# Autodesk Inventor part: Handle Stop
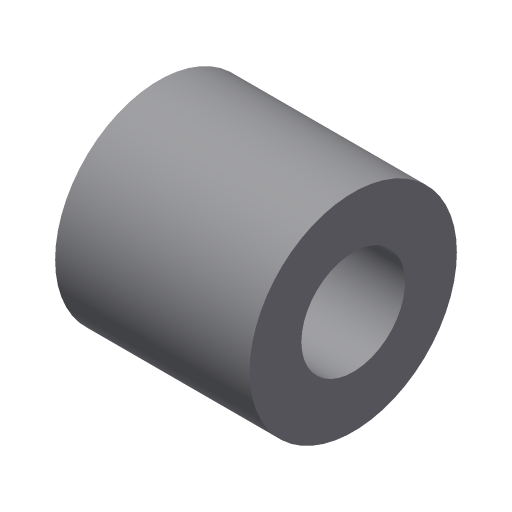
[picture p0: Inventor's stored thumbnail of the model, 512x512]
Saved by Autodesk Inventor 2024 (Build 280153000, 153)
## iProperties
Shininess: 77.0
Length Units: 11269
Angle Units: 11279
Time Units: 11290
Mass Units: 11283
Length Display Precision: 3
Angle Display Precision: 2
Compacted: True
Created: 2002-02
Part Number: Handle Stop
Document SubType Name: Modeling
Designer: ***
Density: 1 g/cm^3
Material: Generic
Mass: 2.36248 g
Surface Area: 14.8283 cm^2
Volume: 2.36248 cm^3
Appearance: Default
Density: 0.0
Volumn: 0.0
Area: 0.0
PropertySet Name: Model Information
Control State: 0
Master: False
Checked Out: False
Author: ***
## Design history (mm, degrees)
sketch "Sketch1"
  geometry: L1 (0, 0)-(0, -2); L2 (0, -2)-(8, -2); L3 (8, -2)-(8, 13); L4 (8, 13)-(4, 13); L5 (4, 13)-(4, 0); L6 (4, 0)-(0, 0)
  constraints: 12 end point, 4 parallel, 1 perpendicular, 1 vertical
  dimensions: "d0" = 16 diameter of L3 L1; "d1" = 8 diameter of L5 L1; "d2" = 2 distance of L1.start L1.end; "d3" = 15 distance of L2.end L3.end
revolve "Revolution1" sketch "Sketch1" stored, may be unused: angle "d4" = 90 deg
body "Solid1"
